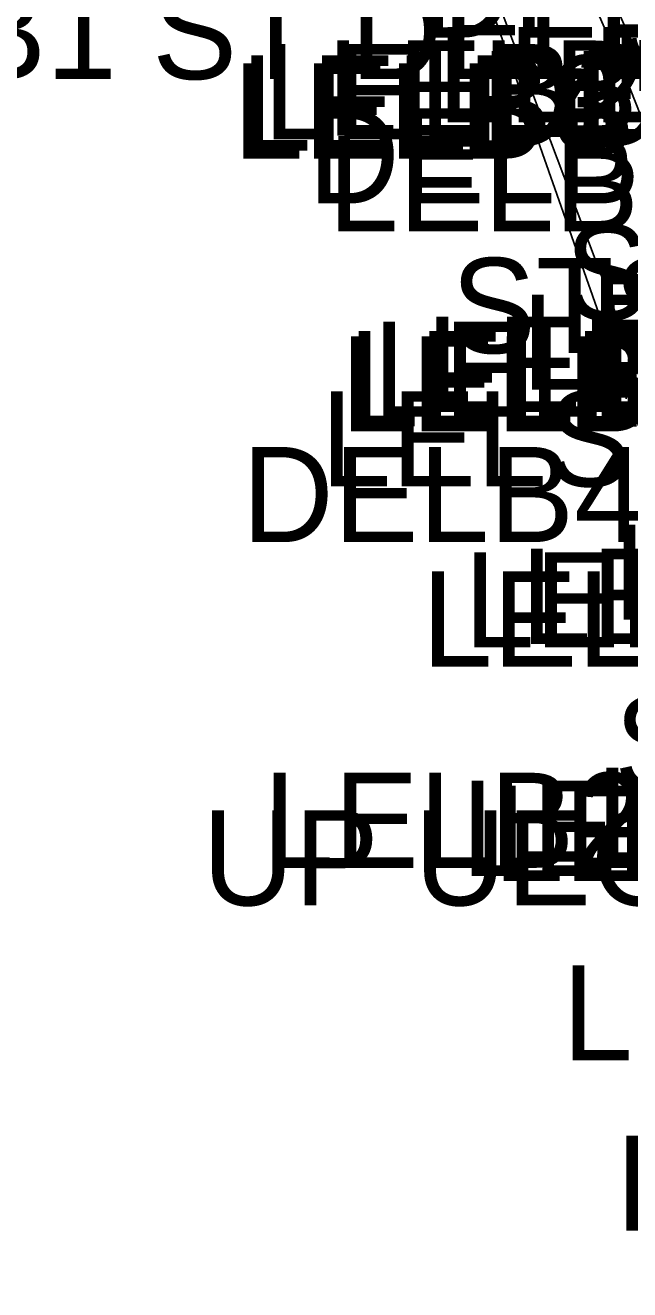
# Model space of a CAD drawing. Extents: x 1040177 to 1042343, y 1125540 to 1129143.
# Drawn here: x 1040399.9 to 1040463.4, y 1128162.7 to 1128295.6 of the extents above; entities that cross this region are included whole.
import ezdxf

# ---------------------------------------------------------------- set-up
doc = ezdxf.new("R2010")
doc.units = 0
for name, color, linetype in [('CDEFAULT', 7, 'Continuous'), ('COCOD', 7, 'Continuous'), ('COELE', 7, 'Continuous'), ('COPNT', 7, 'Continuous'), ('LABL', 7, 'Continuous'), ('LELB', 7, 'Continuous'), ('LELS', 7, 'Continuous'), ('UEO', 7, 'Continuous')]:
    doc.layers.add(name, color=color, linetype=linetype)

msp = doc.modelspace()

# ---------------------------------------------------------------- linework, layer by layer
at = {"layer": 'LABL'}
for points in [[(1040463.02, 1128257.15), (1040444.53, 1128309.71)], [(1040477.81, 1128216.23), (1040463.02, 1128257.15)]]:
    msp.add_lwpolyline(points, dxfattribs=at)
at = {"layer": 'LELB'}
for points in [[(1040556.06, 1128033.92), (1040548.57, 1128053.68), (1040541.49, 1128077.3), (1040531.67, 1128100.43), (1040520.61, 1128126.06), (1040516.58, 1128143.34), (1040506.89, 1128174.28), (1040498.03, 1128196.84), (1040490.79, 1128215.69), (1040483.27, 1128238.22), (1040475.53, 1128263.46), (1040464.25, 1128292.43), (1040455.52, 1128312.02), (1040438.72, 1128340.45), (1040438.45, 1128340.97), (1040437.13, 1128341.43), (1040434.71, 1128340.72), (1040422.09, 1128339.34)], [(1040554.52, 1128033.3), (1040547.08, 1128053.47), (1040539.58, 1128076.27), (1040529.8, 1128099.73), (1040518.96, 1128125.65), (1040515.08, 1128142.88), (1040473.71, 1128262.92), (1040462.39, 1128291.59), (1040453.72, 1128311.36), (1040437.26, 1128336.15), (1040435.49, 1128337), (1040422.35, 1128335.42)]]:
    msp.add_lwpolyline(points, dxfattribs=at)
at = {"layer": 'LELS'}
for points in [[(1040462.24, 1128257.15), (1040463.02, 1128257.15)], [(1040463.02, 1128257.94), (1040463.02, 1128257.15)], [(1040463.02, 1128257.15), (1040463.81, 1128257.15)], [(1040463.02, 1128257.15), (1040463.02, 1128256.36)]]:
    msp.add_lwpolyline(points, dxfattribs=at)
at = {"layer": 'UEO'}
msp.add_lwpolyline([(1040632.97, 1128031.81), (1040554.71, 1128002.16), (1040556.16, 1128023.89), (1040539.16, 1128062.72), (1040481.62, 1128213.13), (1040410.07, 1128402.7), (1040335.48, 1128595.35)], dxfattribs=at)

# ---------------------------------------------------------------- texts
at = {"layer": 'CDEFAULT'}
for height, p in [(10, (1040460.98, 1128287.43)), (10, (1040461.94, 1128287.91)), (10, (1040459.12, 1128286.59)), (0.0781, (1040462.37, 1128291.55)), (10, (1040459.76, 1128252.15)), (0.0781, (1040463, 1128257.11))]:
    msp.add_text('+', height=height, dxfattribs=at).set_placement(p)
at = {"layer": 'COCOD'}
for s, height, p in [('DELB3 ST', 10, (1040441.42, 1128294.31)), ('DELB1 ST DELB2 ST', 10, (1040367.13, 1128289.94)), ('LELB', 10, (1040443.18, 1128285.4)), ('LELB2', 10, (1040424.87, 1128283.63)), ('LELB1', 10, (1040431.56, 1128284)), ('DD', 10, (1040447.81, 1128282.91)), ('LELB4', 10, (1040421.69, 1128281.59)), ('LELB3', 10, (1040422.52, 1128282.43)), ('LELB4', 0.0781, (1040462.15, 1128291.51)), ('DELB1 DELB2', 10, (1040429.58, 1128276.88)), ('LELB1 DELB1', 10, (1040431.67, 1128273.96)), ('STPBY', 10, (1040456.57, 1128264.64)), ('STSEW', 10, (1040444.61, 1128261.15)), ('RDU', 10, (1040459.29, 1128259.45)), ('LELB', 10, (1040452.03, 1128257.31)), ('LELB2', 10, (1040436.4, 1128254.47)), ('LELB1', 10, (1040441.98, 1128254.98)), ('DD', 10, (1040459.37, 1128254.06)), ('LELB4', 10, (1040433, 1128252.92)), ('LELB3', 10, (1040433.8, 1128253.46)), ('LELS', 10, (1040430.9, 1128247.15)), ('LELS LABL ST JPT 2614', 0.0781, (1040461.96, 1128257.07)), ('DELB4 ST DELB2 ST', 10, (1040422.63, 1128241.3)), ('LELB', 10, (1040461.66, 1128233.13)), ('LELB2', 10, (1040445.97, 1128230.23)), ('LELB1', 10, (1040451.92, 1128230.6)), ('LELB3', 10, (1040441.54, 1128228.22)), ('STSEW', 10, (1040461.78, 1128215.11)), ('LELB2 ST', 10, (1040424.88, 1128207.07)), ('LELB1', 10, (1040459.85, 1128207.58)), ('LELS', 10, (1040445.68, 1128206.23)), ('LELB3', 10, (1040449.06, 1128205.69)), ('UP UEO2', 10, (1040418.47, 1128203.13)), ('LELB3', 10, (1040456.3, 1128186.84)), ('LELS', 10, (1040461.95, 1128168.95))]:
    msp.add_text(s, height=height, dxfattribs=at).set_placement(p)
at = {"layer": 'COELE'}
for s, height, p in [('392.628', 10, (1040462.39, 1128291.59)), ('392.628', 0.0781, (1040462.39, 1128291.59)), ('392.481', 0.0781, (1040463.02, 1128257.15))]:
    msp.add_text(s, height=height, dxfattribs=at).set_placement(p)
at = {"layer": 'COPNT'}
for s, p in [('1415', (1040462.39, 1128291.51)), ('2613', (1040463.02, 1128257.07))]:
    msp.add_text(s, height=0.0781, dxfattribs=at).set_placement(p)

doc.saveas('drawing.dxf')
